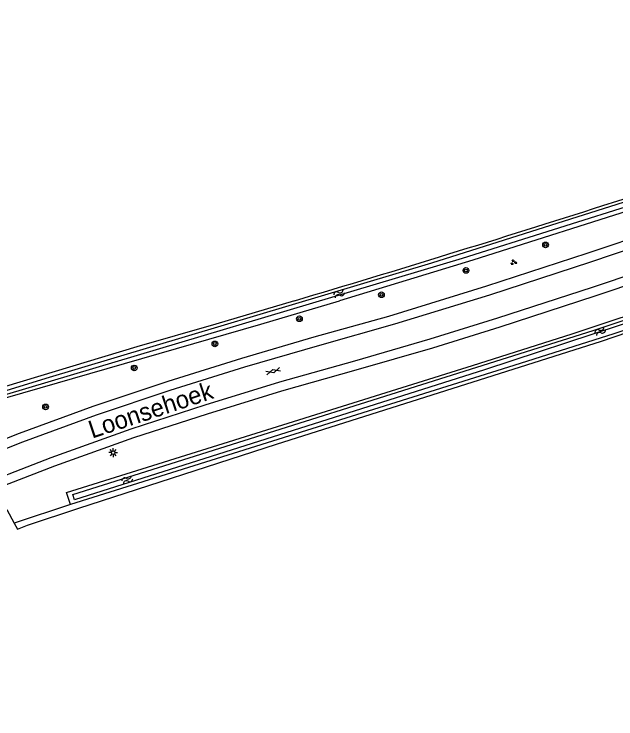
# Model space of a CAD drawing. Extents: x 134297 to 137000, y 403500 to 406000.
# Drawn here: x 136017.8 to 136102.7, y 404441 to 404540.4 of the extents above; entities that cross this region are included whole.
import ezdxf

# ---------------------------------------------------------------- set-up
doc = ezdxf.new("R2010")
doc.units = 0
for name, color, linetype in [('gg-afsc-draadraster', 7, 'Continuous'), ('gg-afsc-erfafscheiding', 7, 'Continuous'), ('gg-afsc-lijn draadraster', 7, 'Continuous'), ('gg-anno-openbare ruimte label', 7, 'Continuous'), ('gg-knt-verharding', 7, 'Continuous'), ('gg-knt-verharding nz', 7, 'Continuous'), ('gg-kntw-bovenkant insteek waterloop', 7, 'Continuous'), ('gg-kntw-waterlijn', 7, 'Continuous'), ('gt-grn-groengrens', 7, 'Continuous'), ('gt-symb-boom', 7, 'Continuous'), ('gt-symb-gesloten verharding', 7, 'Continuous'), ('gt-symb-groenvak', 7, 'Continuous'), ('gt-symb-lichtmast', 7, 'Continuous'), ('gt-symb-watersymbool', 7, 'Continuous')]:
    doc.layers.add(name, color=color, linetype=linetype)

# ---------------------------------------------------------------- blocks, each defined once
blk = doc.blocks.new('gt0-BOOM')
at = {"layer": 'gt-symb-boom'}
for radius in [0.4, 0.2]:
    blk.add_circle((0, 0), radius, dxfattribs=at)
blk = doc.blocks.new('gt0-GRVAK')
at = {"layer": 'gt-symb-groenvak'}
for p, q in [((-0.11, 0.189), (-0.228, 0.24)), ((-0.182, 0.153), (0.088, 0.153)), ((-0.091, 0.211), (-0.156, 0.322)), ((-0.047, 0.214), (-0.047, 0.393)), ((-0.004, 0.211), (0.061, 0.322)), ((0.015, 0.189), (0.133, 0.24)), ((0.262, -0.052), (0.197, 0.059)), ((0.305, -0.049), (0.305, 0.13)), ((0.349, -0.052), (0.414, 0.059)), ((-0.245, -0.228), (-0.363, -0.177)), ((-0.318, -0.264), (-0.047, -0.264)), ((-0.226, -0.206), (-0.291, -0.095)), ((-0.183, -0.203), (-0.183, -0.024)), ((-0.139, -0.206), (-0.074, -0.095)), ((-0.12, -0.228), (-0.002, -0.177)), ((0.243, -0.074), (0.125, -0.023)), ((0.17, -0.11), (0.441, -0.11)), ((0.368, -0.074), (0.486, -0.023))]:
    blk.add_line(p, q, dxfattribs=at)
blk = doc.blocks.new('gt0-WA')
at = {"layer": 'gt-symb-watersymbool'}
for centre, start, end in [((-0.323, 0.022), 28.07249, 151.92751), ((0.427, 0.422), 208.07248, 331.92751), ((-0.323, -0.428), 28.07249, 151.92751), ((0.427, -0.028), 208.07248, 331.92751)]:
    blk.add_arc(centre, 0.425, start, end, dxfattribs=at)
blk = doc.blocks.new('gt0-LMAST')
at = {"layer": 'gt-symb-lichtmast'}
for p, q in [((-0.182, 0.173), (-0.447, 0.438)), ((-0.005, 0.246), (-0.005, 0.621)), ((0.172, 0.173), (0.437, 0.438)), ((-0.255, -0.004), (-0.63, -0.004)), ((-0.182, -0.181), (-0.447, -0.446)), ((-0.005, -0.254), (-0.005, -0.629)), ((0.437, -0.446), (0.172, -0.181)), ((0.245, -0.004), (0.62, -0.004))]:
    blk.add_line(p, q, dxfattribs=at)
blk.add_circle((-0.005, -0.004), 0.25, dxfattribs=at)
blk = doc.blocks.new('gt0-GESVH1')
at = {"layer": 'gt-symb-gesloten verharding'}
for p, q in [((-0.992, -0.261), (0.008, 0.239)), ((0.008, -0.261), (-0.992, 0.239)), ((0.008, 0.239), (1.008, -0.261)), ((1.008, 0.239), (0.008, -0.261))]:
    blk.add_line(p, q, dxfattribs=at)

msp = doc.modelspace()

# ---------------------------------------------------------------- linework, layer by layer
at = {"layer": 'gg-afsc-draadraster'}
msp.add_lwpolyline([(136026.996, 404470.755), (136054.868, 404479.769), (136100.689, 404494.304), (136117.791, 404500.098), (136188.907, 404524.968), (136192.836, 404525.942), (136197.237, 404526.466), (136206.062, 404526.859), (136212.489, 404527.78), (136214.079, 404527.216), (136216.903, 404521.125), (136220.142, 404513.532), (136226.744, 404497.618), (136232.397, 404483.416)], dxfattribs=at)
at = {"layer": 'gg-afsc-erfafscheiding'}
msp.add_line((136017.857, 404468.649), (136018.323, 404467.787), dxfattribs=at)
for points in [[(135957.535, 404441.037), (135961.118, 404443.87), (135967.973, 404448.602), (135982.066, 404456.53), (135989.168, 404460.212), (135996.701, 404463.841), (136003.682, 404466.94), (136011.429, 404470.037), (136016.827, 404470.553), (136017.857, 404468.649)], [(136018.323, 404467.787), (136019.727, 404468.362), (136026.996, 404470.755)]]:
    msp.add_lwpolyline(points, dxfattribs=at)
at = {"layer": 'gg-afsc-lijn draadraster'}
msp.add_lwpolyline([(136026.996, 404470.755), (136054.868, 404479.769), (136100.689, 404494.304), (136117.791, 404500.098), (136188.907, 404524.968), (136192.836, 404525.942), (136197.237, 404526.466), (136206.062, 404526.859), (136212.489, 404527.78), (136214.079, 404527.216), (136216.903, 404521.125), (136220.142, 404513.532), (136226.744, 404497.618), (136232.397, 404483.416)], dxfattribs=at)
at = {"layer": 'gg-knt-verharding'}
for points in [[(136197.492, 404535.452), (136195.129, 404534.58), (136162.905, 404522.967), (136127.357, 404510.1), (136113.621, 404505.301), (136099.758, 404500.626), (136086.34, 404496.276), (136076.86, 404493.324), (136066.068, 404490.194), (136055.557, 404487.242), (136045.09, 404483.996), (136034.702, 404480.643), (136023.556, 404476.678), (136011.231, 404471.899), (136004.741, 404469.148), (135995.868, 404465.089), (135985.915, 404460.265), (135976.35, 404455.353), (135965.544, 404449.333), (135957.736, 404444.758)], [(136108.202, 404509.869), (136098.642, 404506.633), (136084.476, 404502.047), (136070.647, 404497.785), (136060.142, 404494.867), (136049.916, 404491.849), (136039.522, 404488.608), (136028.948, 404485.069), (136018.545, 404481.255), (136009.16, 404477.577), (135999.862, 404473.646), (135990.66, 404469.366), (135981.821, 404465.018), (135975.54, 404461.77), (135967.959, 404457.676), (135960.576, 404453.482), (135954.605, 404449.976)]]:
    msp.add_lwpolyline(points, dxfattribs=at)
at = {"layer": 'gg-knt-verharding nz'}
for points in [[(136197.155, 404540.403), (136161.454, 404527.525), (136124.761, 404514.251), (136111.521, 404509.601), (136099.131, 404505.428), (136084.901, 404500.783), (136071.516, 404496.674), (136060.904, 404493.693), (136050.354, 404490.609), (136039.81, 404487.339), (136029.404, 404483.842), (136019.026, 404480.06), (136009.725, 404476.398), (136000.5, 404472.453), (135991.397, 404468.234), (135983.333, 404464.286), (135976.204, 404460.632), (135968.253, 404456.351), (135961.287, 404452.397), (135955.274, 404448.861)], [(136197.377, 404536.826), (136126.863, 404511.309), (136112.69, 404506.322), (136099.401, 404501.864), (136086.048, 404497.548), (136076.48, 404494.56), (136065.87, 404491.476), (136055.281, 404488.499), (136044.762, 404485.252), (136034.329, 404481.864), (136023.036, 404477.858), (136010.897, 404473.142), (136004.485, 404470.444), (135995.355, 404466.291), (135985.463, 404461.467), (135975.706, 404456.457), (135965.21, 404450.623), (135957.075, 404445.859)]]:
    msp.add_lwpolyline(points, dxfattribs=at)
at = {"layer": 'gg-kntw-bovenkant insteek waterloop'}
msp.add_line((136100.913, 404513.415), (136107.065, 404515.387), dxfattribs=at)
for points in [[(136107.065, 404515.387), (136107.424, 404513.595), (136082.549, 404505.721), (136063.769, 404500)], [(136016.614, 404486.324), (136052.67, 404496.711), (136063.769, 404500)], [(136057.392, 404500), (136046.293, 404496.711), (136035.176, 404493.485), (136016.618, 404487.882)], [(136025.795, 404471.241), (136025.225, 404472.963), (136082.488, 404490.858), (136096.565, 404495.348), (136110.59, 404500)], [(136116.453, 404500), (136102.428, 404495.348), (136088.351, 404490.858), (136025.795, 404471.241)]]:
    msp.add_lwpolyline(points, dxfattribs=at)
msp.add_arc((135478.586, 406455.067), 2038.946, 286.491607, 287.771384, dxfattribs=at)
at = {"layer": 'gg-kntw-waterlijn'}
for points in [[(136026.118, 404472.654), (136099.53, 404495.774), (136116.162, 404501.344), (136137.788, 404508.822), (136159.931, 404516.915), (136185.605, 404526.086), (136185.843, 404525.421), (136174.22, 404521.269), (136134.804, 404507.064), (136122.464, 404502.824), (136084.209, 404490.249), (136026.345, 404471.915), (136026.118, 404472.654)], [(136016.734, 404487.349), (136022.351, 404489.088), (136076.781, 404505.341), (136106.631, 404514.778), (136106.733, 404514.037), (136081.044, 404505.966), (136016.772, 404486.749)]]:
    msp.add_lwpolyline(points, dxfattribs=at)
at = {"layer": 'gt-grn-groengrens'}
msp.add_line((136025.795, 404471.241), (136017.857, 404468.649), dxfattribs=at)

# ---------------------------------------------------------------- block references
at = {"layer": 'gt-symb-boom'}
for p in [(136092.807, 404507.87), (136081.583, 404504.259), (136069.665, 404500.833), (136058.09, 404497.449), (136046.167, 404493.904), (136034.792, 404490.512), (136022.286, 404485.026)]:
    msp.add_blockref('gt0-BOOM', p, dxfattribs=at)
at = {"layer": 'gt-symb-gesloten verharding', "rotation": 16.07917237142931}
msp.add_blockref('gt0-GESVH1', (136054.393, 404490.059), dxfattribs=at)
at = {"layer": 'gt-symb-groenvak'}
msp.add_blockref('gt0-GRVAK', (136088.298, 404505.402), dxfattribs=at)
at = {"layer": 'gt-symb-lichtmast'}
msp.add_blockref('gt0-LMAST', (136031.823, 404478.576), dxfattribs=at)
at = {"layer": 'gt-symb-watersymbool'}
for p, rotation in [((136063.743, 404500.993), -152.02527008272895), ((136100.565, 404495.698), -146.99293824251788), ((136033.862, 404474.763), -152.02527007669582)]:
    msp.add_blockref('gt0-WA', p, dxfattribs=dict(at, rotation=rotation))

# ---------------------------------------------------------------- texts
at = {"layer": 'gg-anno-openbare ruimte label'}
msp.add_text('Loonsehoek', height=2.5, rotation=18.3, dxfattribs=at).set_placement((136028.846, 404480.549))

doc.saveas('drawing.dxf')
